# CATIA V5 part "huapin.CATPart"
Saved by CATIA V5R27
Part number: flower
Material "Water": density 1000 kg/m3
Material "Summer sky"
Material "Fire Red": density 7860 kg/m3, Young's modulus 2e+11 Pa, Poisson ratio 0.266
Bounding box of the stored display mesh (mm): x -45.563 to 45.563, y -45.563 to 61.991, z 0 to 139.66
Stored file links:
  C:\Users\user\Desktop\180131230李文彬\huapin.CATPart
  E:\Program Files\Dassault Systemes\B27\win_b64\startup\materials\Catalog.CATMaterial
  E:\Program Files\Dassault Systemes\B27\win_b64\startup\materials\teak_2.jpg
  E:\Program Files\Dassault Systemes\B27\win_b64\startup\materials\cedar.jpg
  E:\Program Files\Dassault Systemes\B27\win_b64\startup\materials\blue_env_512x512.jpg
  E:\Program Files\Dassault Systemes\B27\win_b64\startup\materials\DS_star.jpg
  E:\Program Files\Dassault Systemes\B27\win_b64\startup\materials\summer_sky.jpg
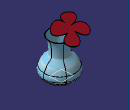
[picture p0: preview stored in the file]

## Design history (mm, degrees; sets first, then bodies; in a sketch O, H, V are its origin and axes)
Body1 (main body), material "Summer sky"
  Plane1: type Offset, RefPlane xy-plane, Offset 20
  Plane2: type Offset, RefPlane Plane1, Offset 20
  Plane3: type Offset, RefPlane Plane2, Offset 20
  Plane4: type Offset, RefPlane Plane3, Offset 20
  Plane5: type Offset, RefPlane Plane4, Offset 20
  Sketch1 on Plane5, origin (0, 0, 100), H (1, 0, 0), V (0, 1, 0)
    circle A1 centre (0, 0) radius 29.8266
  Sketch2 on Plane4, origin (0, 0, 80), H (1, 0, 0), V (0, 1, 0)
    circle A1 centre (0, 0) radius 23.0726
  Sketch3 on Plane3, origin (0, 0, 60), H (1, 0, 0), V (0, 1, 0)
    circle A1 centre (0, 0) radius 21.9749
  Sketch4 on Plane2, origin (0, 0, 40), H (1, 0, 0), V (0, 1, 0)
    circle A1 centre (0, 0) radius 37.8812
  Sketch5 on Plane1, origin (0, 0, 20), H (1, 0, 0), V (0, 1, 0)
    circle A1 centre (0, 0) radius 45.607
  Sketch6 on xy-plane, origin (0, 0, 0), H (1, 0, 0), V (0, 1, 0)
    circle A1 centre (0, 0) radius 31.6229
  Loft1: solid, Sections (Sketch1; Sketch2; Sketch3; Sketch4; Sketch5; Sketch6)
  Shell1: ExtOffset 0, Face face of Loft1, IntOffset 1
Body2, material "Water"
  Sketch7 on yz-plane, origin (0, 0, 0), H (0, 1, 0), V (0, 0, 1)
    axis line L1 (0, 117.0904) -> (0, -14.88)
    point P1 (0, 117.0904)
    line L2 (0, 0) -> (30.5626, 0)
    line L3 (30.5626, 0) -> (41.5502, 9.897)
    line L4 (41.5502, 9.897) -> (44.4279, 15.6349)
    line L5 (44.4279, 15.6349) -> (44.4279, 21.6335)
    line L6 (44.4279, 21.6335) -> (43.1199, 28.9362)
    line L7 (43.1199, 28.9362) -> (0, 28.9362)
    point P8 (0, 28.9362)
    line L8 (0, 28.9362) -> (0, 0)
    coincidence: P1 V, P8 L1
    vertical: L1 V, L5 V, L8 V
    horizontal: L2 H, L7 H
  Shaft1: profile Sketch7, axis Sketch7.L1, angle 360
Body3, material "Fire Red"
  Sketch8 on yz-plane, origin (0, 0, 0), H (0, 1, 0), V (0, 0, 1)
    spline S1 through (4.925, 3.3767) (15.651, 101.1809) (24.5457, 125.9579)
    point P1 (24.5457, 125.9579)
    point P2 (24.5457, 125.9579)
    coincidence: P1 P2
  Plane6: type Normal, Curve Sketch8, RefPoint vertex of Sketch8
  Sketch9 on Plane6, origin (0, -0.2087, 3.0221), H (-1, 0, 0), V (0, 0.9976, 0.0689)
    circle A1 centre (0, 4.9123) radius 1
    point P1 (0, 4.9123)
    radius A1 = 1
    coincidence: P1 V
  Rib1: profile Sketch9, centre curve Sketch8
  Plane7: type OffsetPt, RefPlane zx-plane, RefPoint Sketch8.P2
  Plane8: type Normal, Curve Sketch8, RefPoint Sketch8.P2
  Sketch10 on Plane8, origin (0, 48.2205, 116.1272), H (1, 0, 0), V (0, -0.9235, 0.3835)
    spline S1 through (-4.3423, 41.7545) (-19.2273, 61.1433) (-37.8855, 41.7545) (-12.0228, 30.6751) (-40.4521, 21.5134) (-23.8706, -3.9187) (-8.5786, 13.9217) (2.1878, -12.1777) (28.996, 6.7624) (7.7842, 19.0587) (34.5873, 27.8468) (18.1132, 54.0973) (-4.3423, 41.7545)
    point P1 (-4.3423, 41.7545)
    point P2 (-4.3423, 41.7545)
    coincidence: P1 P2
  Pad1: profile Sketch10, direction (0, -0.3835, -0.9235), length 1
